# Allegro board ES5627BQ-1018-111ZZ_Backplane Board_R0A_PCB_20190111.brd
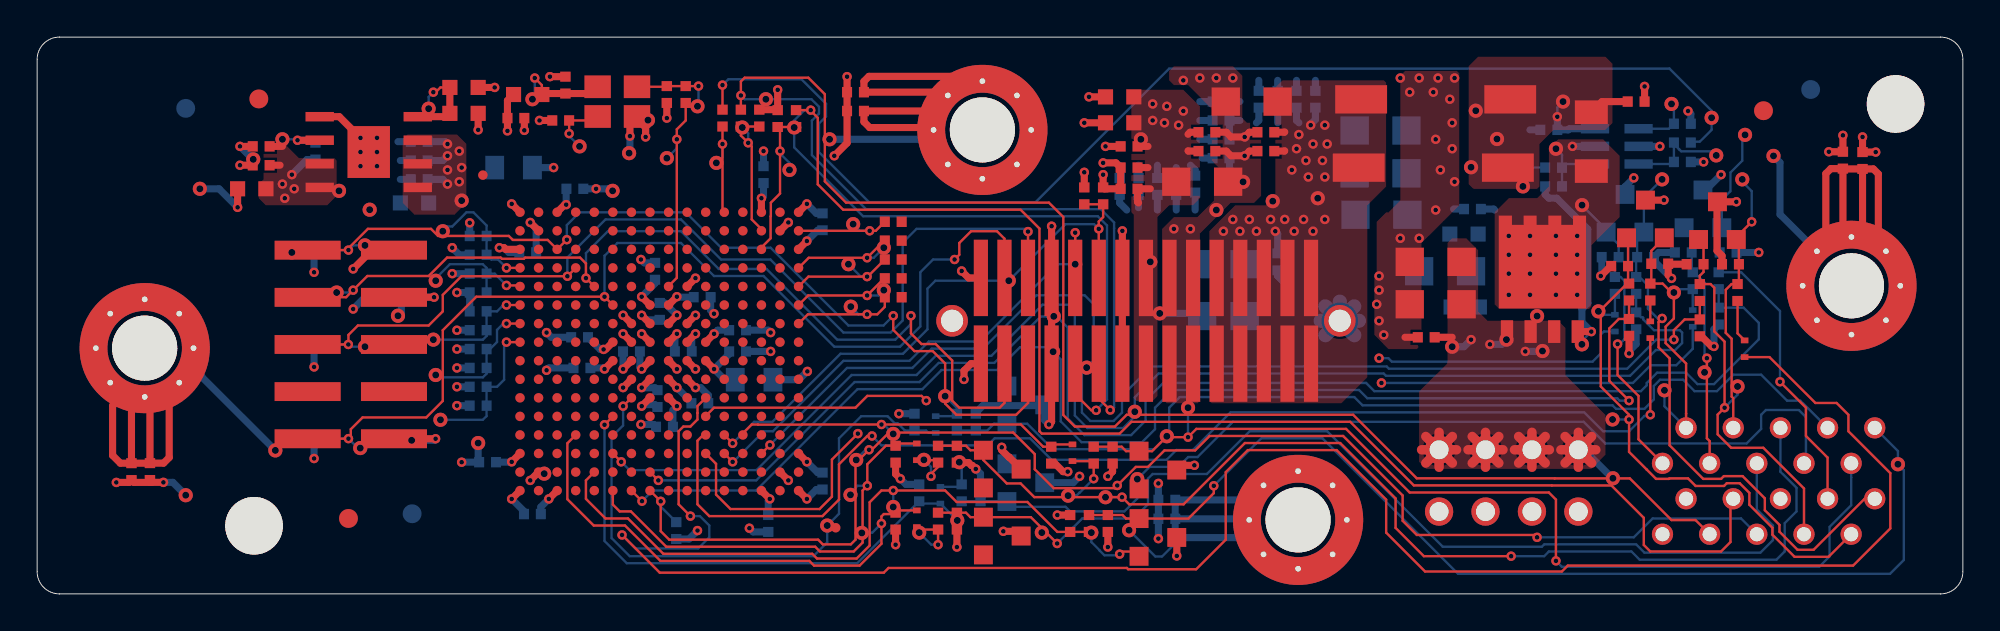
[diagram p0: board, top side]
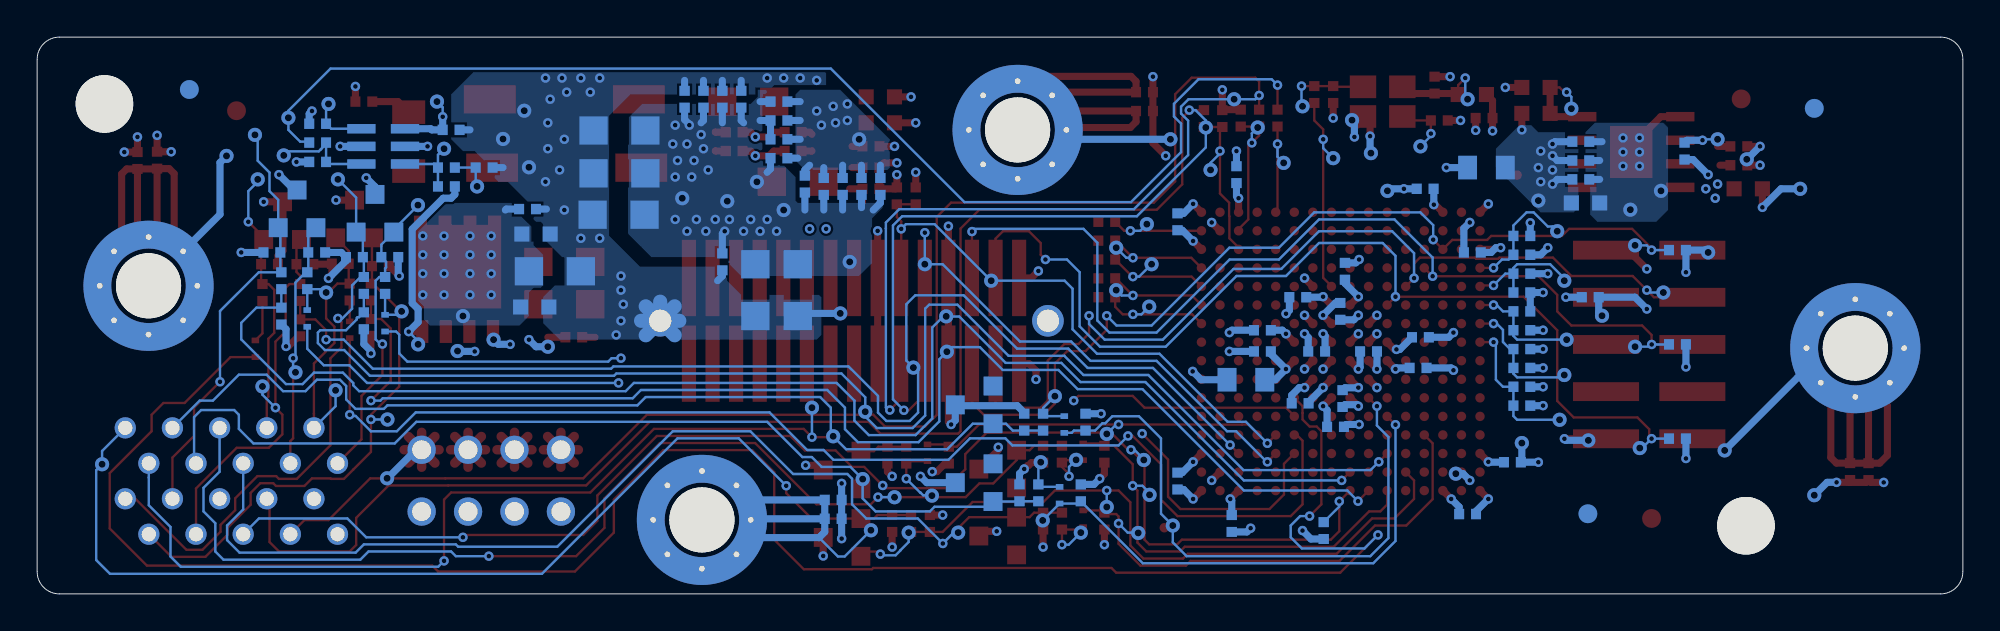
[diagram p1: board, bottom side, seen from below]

Outline 103.7 x 30 mm; copper layers: TOP, G2, V3, BOTTOM. Coordinates in mm from the lower left corner of the outline.
Outline path: 0,28.8 0,1.2 arc(0.35,0.35) 1.2,0 102.5,0 arc(103.35,0.35) 103.7,1.2 103.7,28.8 arc(103.35,29.65) 102.5,30 1.2,30 arc(0.35,29.65) 0,28.8

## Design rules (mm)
nets with their own width: min track width 0.381; nets GND

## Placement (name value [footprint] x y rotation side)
C2  100pF  [CC0402]  88.65 18.4 90 bottom
C3  100pF  [CC0402]  91.06 18.4 270 bottom
C7  100pF  [CC0402]  91.19 17.76 270 top
C8  100pF  [CC0402]  89.28 17.76 270 top
C9  100pF  [CC0402]  57.91 7.48 0 top
C10  100pF  [CC0402]  87.38 17.79 90 top
C11  100pF  [CC0402]  85.22 17.66 270 top
C12  100pF  [CC0402]  50.8 5.44 0 bottom
C13  100pF  [CC0402]  84.71 18.14 90 bottom
C14  100pF  [CC0402]  86.61 18.14 270 bottom
C16  100pF  [CC0402]  57.66 3.79 0 top
C17  100pF  [CC0402]  49.53 3.92 0 top
C22  100pF  [CC0402]  50.55 9.25 0 bottom
C23  100pF  [CC0402]  49.53 7.53 0 top
C31  0.1uF  [CC0402]  98.3 23.35 180 top
C32  0.1uF/16V  [CC0402]  20.07 15.99 270 bottom
C33  0.1uF  [CC0402]  44.07 26.02 270 top
C35  0.1uF  [CC0402]  44.07 27.03 270 top
C36  0.1uF  [CC0402]  97.24 23.37 180 top
C37  0.1uF/16V  [CC0402]  65.79 26.65 180 bottom
C38  0.1uF/16V  [CC0402]  63.75 24.49 270 bottom
C39  0.1uF/16V  [CC0402]  63.75 25.51 270 bottom
C40  0.1uF/16V  [CC0402]  63.75 26.53 270 bottom
C41  0.1uF/16V  [CC0402]  58.29 21.95 180 bottom
C42  22uF/16V  [CC1206]  75.82 17.38 270 bottom
C44  0.1uF/16V  [CC0402]  77.29 20.74 90 bottom
C48  0.1uF  [CC0402]  60.83 4.05 90 bottom
C49  0.1uF/16V  [CC0402]  86.11 26.53 270 top
C51  0.1uF/16V  [CC0402]  28.45 27.42 180 top
C52  0.1uF  [CC0402]  62.99 24.88 270 top
C53  0.01uF  [CC0402]  58.8 21.83 90 top
C54  0.1uF  [CC0402]  58.8 22.97 90 top
C55  @10pF  [CC0402]  33.91 26.91 180 top
C56  0.1uF/16V  [CC0402]  25.78 25.64 90 top
C57  22uF  [CC1206]  62.74 22.21 90 top
C58  0.1uF  [CC0402]  6.08 6.59 0 top
C59  0.1uF/16V  [CC0402]  20.57 22.34 90 bottom
C60  0.1uF/16V  [CC0402]  20.57 24.37 90 bottom
C61  0.1uF/16V  [CC0402]  20.57 23.35 90 bottom
C63  22uF/6.3V  [CC0603]  20.32 21.07 90 bottom
C65  0.1uF/16V  [CC0402]  74.8 13.83 270 top
C66  22uF/16V  [CC1206]  75.31 15.6 90 top
C67  22uF/16V  [CC1206]  75.31 17.89 90 top
C68  0.1uF  [CC0402]  60.83 5.06 90 bottom
C69  0.1uF  [CC0402]  5.08 6.59 0 top
C71  22uF/6.3V  [CC0603]  11.56 21.83 270 top
C74  0.1uF/16V  [CC0402]  12.06 24.11 270 top
C75  0.1uF/16V  [CC0402]  12.06 23.1 270 top
C76  0.1uF/16V  [CC0402]  81.41 25 90 bottom
C77  0.22uF  [CC0402]  88.6 25.33 270 bottom
C78  0.01uF/25V  [CC0402]  79.63 22.97 270 bottom
C79  1uF  [CC0603]  76.9 15.46 90 bottom
C80  10uF  [CC0603]  76.83 19.39 90 bottom
CB1  22uF/16V  [CC1206]  65.02 16.37 0 bottom
CB2  22uF/16V  [CC1206]  72.39 20.43 90 bottom
CB3  22uF/16V  [CC1206]  65.41 26.53 90 top
CB4  22uF/16V  [CC1206]  62.74 16.37 0 bottom
CB5  22uF/16V  [CC1206]  72.34 22.66 90 bottom
CB6  22uF/16V  [CC1206]  72.34 24.97 90 bottom
CB7  0.1uF/16V  [CC0402]  66.17 24.88 270 top
CB8  0.1uF/16V  [CC0402]  61.34 21.95 180 bottom
CB9  0.1uF/16V  [CC0402]  59.31 21.95 180 bottom
CB10  0.1uF/16V  [CC0402]  63.75 23.48 270 bottom
CB11  0.1uF/16V  [CC0402]  60.33 21.95 180 bottom
CB12  0.1uF/16V  [CC0402]  62.36 22.08 180 bottom
CB13  0.1uF/16V  [CC0402]  68.83 26.65 0 bottom
CB14  0.1uF/16V  [CC0402]  66.17 23.86 270 top
CB15  0.1uF/16V  [CC0402]  66.8 17.89 180 bottom
CB16  0.1uF/16V  [CC0402]  67.82 26.65 0 bottom
CB17  0.1uF/16V  [CC0402]  66.8 26.65 0 bottom
CB18  0.1uF/16V  [CC0402]  26.67 4.3 90 bottom
CB19  0.1uF/16V  [CC0402]  29.21 13.83 90 bottom
CB20  0.1uF/16V  [CC0402]  29.34 12.18 90 bottom
CB21  0.1uF/16V  [CC0402]  33.27 17.38 0 bottom
CB22  0.1uF/16V  [CC0402]  42.29 20.05 0 bottom
CB23  0.1uF/16V  [CC0402]  42.29 6.08 180 bottom
CB24  0.1uF/16V  [CC0402]  39.37 3.79 180 bottom
CB25  22uF/6.3V  [CC0805]  38.61 11.54 270 bottom
CB26  0.1uF/16V  [CC0402]  35.69 10.27 270 bottom
CB27  0.1uF/16V  [CC0402]  33.78 9 90 bottom
CB28  0.1uF/16V  [CC0402]  33.53 15.22 0 bottom
CB29  0.1uF/16V  [CC0402]  24.26 7.1 90 bottom
CB30  0.1uF/16V  [CC0402]  32 13.06 90 bottom
CB31  0.1uF/16V  [CC0402]  28.96 21.83 270 bottom
CB32  0.1uF/16V  [CC0402]  34.8 13.06 270 bottom
CB33  22uF/6.3V  [CC0805]  25.65 22.97 270 bottom
CB34  0.1uF/16V  [CC0402]  37.72 14.21 270 bottom
CB35  0.1uF/16V  [CC0402]  35.81 15.99 270 bottom
CB36  0.1uF/16V  [CC0402]  33.4 10.52 0 bottom
CB37  0.1uF/16V  [CC0402]  39.12 22.59 0 bottom
CB38  0.1uF/16V  [CC0402]  26.42 18.4 270 bottom
CB39  0.1uF/16V  [CC0402]  37.72 13.06 270 bottom
CB54  1000pF  [CC0402]  58.8 24.11 270 top
CB55  0.1uF/16V  [CC0402]  62.99 23.86 90 top
CB56  1uF  [CC0603]  58.29 26.78 270 top
CB57  10uF  [CC0603]  58.29 25.38 270 top
CONN6  PHED-SS010G1ABONE-B140  [CONNM_2D54X4D65_2X5SP_12D7W5L]  16.89 13.44 90 top
CONN56  5-104655-4  [CONN_1D27X4D62_2X15SP_22D14W]  59.71 14.72 180 top
D1  RB720M-30  [SOD923_D9_2SP_D8WD6L]  89.15 14.84 90 bottom
D2  RB720M-30  [SOD923_D9_2SP_D8WD6L]  55.75 7.6 270 top
D3  RB720M-30  [SOD923_D9_2SP_D8WD6L]  91.95 13.21 90 top
D4  RB720M-30  [SOD923_D9_2SP_D8WD6L]  48.64 5.32 90 bottom
D5  RB720M-30  [SOD923_D9_2SP_D8WD6L]  84.96 14.59 90 bottom
D6  RB720M-30  [SOD923_D9_2SP_D8WD6L]  47.37 4.05 270 top
D7  RB720M-30  [SOD923_D9_2SP_D8WD6L]  48.39 9.13 90 bottom
D8  RB720M-30  [SOD923_D9_2SP_D8WD6L]  47.37 7.65 270 top
D9  RB720M-30  [SOD923_D9_2SP_D8WD6L]  86.87 14.23 90 top
H1  SCREW3  [MTH_276C138D_8DP_OSP]  97.7 16.6 0 top
H2  SCREW5  [MTH_276C138D_8DP_OSP]  50.9 25 0 top
H3  SCREW2  [MTH_276C138D_8DP_OSP]  67.9 3.99 0 top
H4  SCREW6  [MTH_276C138D_8DP_OSP]  5.79 13.24 0 top
J8  C214B5-100A  [CONN_1D27X1D91_20DP_28D81W_PIP]  87.22 6.08 0 top
L1  100MHz  10A  [LC3312_1]  75.18 22.97 90 top
L2  100MHz  10A  [LC3312_1]  75.31 26.65 90 top
L3  100MHz/3A/30ohm  [LC0603]  26.42 26.91 270 top
NOREF  -  []  5.79 13.24 0 top
NOREF#2  -  []  0 0 0 top
NOREF#3  -  []  11.68 3.67 0 top
NOREF#4  -  []  67.9 3.99 0 top
NOREF#5  -  []  0.08 17.99 0 top
NOREF#6  -  [unnamed#2]  11.94 26.67 0 top
NOREF#7  -  []  97.7 16.6 0 top
NOREF#8  -  []  75.49 4.44 0 top
NOREF#9  -  []  100.08 26.4 0 top
NOREF#10  -  []  5.79 13.24 0 top
NOREF#11  -  []  103.7 1.2 0 top
NOREF#12  -  [unnamed#2]  92.96 26.04 0 top
NOREF#13  -  []  67.9 3.99 0 top
NOREF#14  -  []  1.2 30 0 top
NOREF#15  -  []  100.08 26.4 0 top
NOREF#16  -  []  97.7 16.6 0 top
NOREF#17  -  []  50.9 25 0 top
NOREF#18  -  []  75.49 4.44 0 top
NOREF#19  -  [unnamed#2]  11.68 3.67 0 top
NOREF#20  -  []  249.81 -104.66 0 top
NOREF#21  -  []  0 0 0 top
NOREF#22  -  []  70.15 14.72 0 top
NOREF#23  -  [unnamed#2]  16.76 4.06 0 top
NOREF#24  -  []  11.68 3.67 0 top
NOREF#25  -  []  70.15 14.72 0 top
NOREF#26  -  []  50.9 25 0 top
NOREF#27  -  []  16.89 13.44 0 top
NOREF#28  -  [unnamed#2]  100.08 26.4 0 top
NOREF#29  -  []  16.89 13.44 0 top
NOREF#30  -  [unnamed#2]  8 26.16 180 bottom
NOREF#31  -  [unnamed#2]  20.19 4.32 180 bottom
NOREF#32  -  [unnamed#2]  95.5 27.18 180 bottom
OSC1  25MHz  [OSC_1D6X2D12_4SP_2D5W3D2L1DH]  31.24 26.52 0 top
Q1  PJMBZ6V2  [SOT23_3SP_C1_C2_A]  89.7 20.75 180 bottom
Q2  PJMBZ6V2  [SOT23_3SP_C1_C2_A]  90.48 20.11 0 top
Q3  PJMBZ6V2  [SOT23_3SP_C1_C2_A]  86.61 20.2 0 top
Q4  PJMBZ6V2  [SOT23_3SP_C1_C2_A]  85.51 20.51 180 bottom
Q5  PJMBZ6V2  [SOT23_3SP_C1_C2_A]  60.35 6.67 270 top
Q6  PJMBZ6V2  [SOT23_3SP_C1_C2_A]  53.24 5.99 90 bottom
Q7  PJMBZ6V2  [SOT23_3SP_C1_C2_A]  60.35 3.04 270 top
Q8  PJMBZ6V2  [SOT23_3SP_C1_C2_A]  51.97 3.12 270 top
Q9  PJMBZ6V2  [SOT23_3SP_C1_C2_A]  53.24 10.18 90 bottom
Q10  PJMBZ6V2  [SOT23_3SP_C1_C2_A]  51.97 6.72 270 top
Q11  N-CH  [SO8_3D75X1D27_5SP]  81.06 16.96 270 top
R1  100  [RC0402]  89.15 16.87 180 bottom
R2  100  [RC0402]  90.55 16.87 0 bottom
R3  100  [RC0402]  91.57 16.24 0 top
R4  100  [RC0402]  89.53 16.24 180 top
R5  100  [RC0402]  56.9 7.48 0 top
R6  100  [RC0402]  49.78 5.44 0 bottom
R7  100  [RC0402]  84.96 16.62 180 bottom
R8  100  [RC0402]  86.11 16.62 0 bottom
R9  100  [RC0402]  48.51 3.92 0 top
R10  100  [RC0402]  49.53 9.25 0 bottom
R11  100  [RC0402]  48.51 7.53 0 top
R12  1K  [RC0402]  90.55 14.97 0 bottom
R13  1K  [RC0402]  89.53 14.33 180 top
R14  1K  [RC0402]  86.11 14.72 0 bottom
R15  100  [RC0402]  85.72 16.26 180 top
R16  100  [RC0402]  86.87 16.26 0 top
R18  100  [RC0402]  56.64 3.79 180 top
R20  4.7K  [RC0402]  54.61 7.48 0 top
R21  1K  [RC0402]  85.72 14.36 180 top
R22  4.7K  [RC0402]  47.5 5.44 0 bottom
R23  4.7K  [RC0402]  34.42 3.41 180 bottom
R24  4.7K  [RC0402]  46.23 3.92 0 top
R25  1K  [RC0402]  55.63 3.79 0 top
R26  4.7K  [RC0402]  47.24 9.25 0 bottom
R28  @0  [RC0402]  46.1 20.05 90 top
R29  @0  [RC0402]  46.1 19.03 90 top
R30  @0  [RC0402]  46.1 18.02 90 top
R31  @0  [RC0402]  46.1 17 90 top
R32  @0  [RC0402]  46.1 15.99 90 top
R33  0  [RC0402]  40.87 25.61 180 top
R34  @4.7K  [RC0402]  39.88 25.61 0 top
R35  0  [RC0402]  37.9 25.64 180 top
R36  @4.7K  [RC0402]  38.89 25.64 0 top
R37  0  [RC0402]  36.91 25.64 180 top
R38  10K  [RC0402]  57.4 21.45 180 top
R39  @10K  [RC0402]  56.39 21.45 0 top
R40  33  [RC0402]  34.92 26.91 180 top
R41  4.7K  [RC0402]  28.19 25.51 90 top
R43  10Kohm  [RC0603]  22.99 27.29 270 top
R44  4.7K  [RC0402]  46.23 7.53 0 top
R45  20Kohm  [RC0603]  22.99 25.89 270 top
R48  10K  [RC0402]  23.75 11.16 90 bottom
R49  @4.7K  [RC0402]  23.75 10.14 270 bottom
R50  4.7K  [RC0402]  23.75 12.18 270 bottom
R51  @10K  [RC0402]  23.75 13.19 90 bottom
R52  10K  [RC0402]  23.75 15.22 90 bottom
R53  @4.7K  [RC0402]  23.75 14.21 270 bottom
R54  4.7K  [RC0402]  23.75 17.26 270 bottom
R55  @10K  [RC0402]  23.75 16.24 90 bottom
R56  @10K  [RC0402]  23.75 18.27 90 bottom
R57  4.7K  [RC0402]  23.75 19.29 270 bottom
R58  10K  [RC0402]  15.37 13.45 90 bottom
R59  1K  [RC0402]  15.37 18.53 270 bottom
R61  4.7K  [RC0402]  14.99 23.86 180 bottom
R62  10K  [RC0402]  15.37 8.37 90 bottom
R63  0.005ohm/1206  [RC1206]  83.69 24.37 0 top
R65  10K  [RC0402]  88.6 24.32 270 bottom
R67  100  [RC0402]  81.66 22.97 90 bottom
R68  100  [RC0402]  81.66 21.95 90 bottom
R69  10K  [RC0402]  88.6 23.28 270 bottom
U1  5M1270ZF256I5N  [FBGA_1D_20C_256SP_17WL]  33.5 13.06 270 top
U2  AP7362-SP-13  [SOP_1D27X5D28_8SP_3D9W4D9L_G1]  17.86 23.81 0 top
U3  ADM4210-1AUJ-RL7  [SOT23_D95X2D35_6SP_1D6W2D9L]  85.06 24.11 270 bottom

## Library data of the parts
C2 C3 C7-C14 C16 C17 C22 C23 = C_NP: room: 31
C31-C33 C35 C36 C42 C44 C48 C51 C52 C54 C56 C58-C61 C63 C65-C69 C71 C74 C75 C77 C79 C80 CB1-CB7 CB13-CB39 CB54-CB57 = C_NP
C37-C41 C49 CB8-CB12 = CAP NP_4
C53 C57 C78 = C_NP: room: VCC10
C55 = C_NP: room: 159
C76 = CAP NP
CONN6 = PINSTICK_MALE_5PX2R
CONN56 = PINHEADER_MALE_15PX2R_G2
D1-D9 = SCHOTTKY1_1
H1-H4 = SKREW
J8 = C214B5-100A_0
L1 L2 = BEAD: room: 50
L3 = BEAD: room: 8
OSC1 = OSC_10
Q1-Q10 = DIODE2_3
Q11 = NMOS1_6
R1 R3 R5-R7 R9-R14 R16 R21 R25 R34 R36 R40 R58 R61-R63 R67 R68 = R: tolerance: 1%
R2 R4 R8 R15 R18 = R: room: 1
R20 R22-R24 R26 R44 = R: room: 26
R28-R33 R35 R37 = R: tolerance: 1%; room: U120
R38 R39 R41 R49 R50 R53 R54 R57 = R: tolerance: 1%; room: U83
R43 R45 R48 R51 R52 R55 R56 R65 R69 = R
R59 = R: tolerance: 1%; room: 41
U1 = CPLD_ALTERA_5M1270_FBGA256
U2 = LDO_DIODES_AP7362
U3 = HOT SWAP_ADI_ADM4210-1AUJ

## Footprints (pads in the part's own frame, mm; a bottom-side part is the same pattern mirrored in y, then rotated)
CC0402
  rect 0.559x0.539 smd: 1(0,0.454) 2(0,-0.454)
CC0603
  rect 0.813x0.813 smd: 1(0,0.762) 2(0,-0.762)
CC0805
  rect 1.27x1.016 smd: 1(0,1.016) 2(0,-1.016)
CC1206
  rect 1.524x1.524 smd: 1(0,1.397) 2(0,-1.397)
CONN_1D27X1D91_20DP_28D81W_PIP
  round 1.143 hole 0.762: 1(0.3,-2.865) 2(1.57,-0.955) 3(2.84,-2.865) 4(4.11,-0.955) 5(5.38,-2.865) 6(6.65,-0.955) 7(7.92,-2.865) 8(9.19,-0.955) 9(10.46,-2.865) 10(11.73,-0.955) 11(11.73,2.865) 12(10.46,0.955) 13(9.19,2.865) 14(7.92,0.955) 15(6.65,2.865) 16(5.38,0.955) 17(4.11,2.865) 18(2.84,0.955) 19(1.57,2.865) 20(0.3,0.955)
  round 1.524 hole 1.016: P1A1(-11.73,1.685) P1A2(-9.23,1.685) P1A3(-6.73,1.685) P1A4(-4.23,1.685) P1B1(-11.73,-1.645) P1B2(-9.23,-1.645) P1B3(-6.73,-1.645) P1B4(-4.23,-1.645)
CONN_1D27X4D62_2X15SP_22D14W
  rect 0.762x4.115 smd: 1(-8.89,-2.31) 2(-8.89,2.31) 3(-7.62,-2.31) 4(-7.62,2.31) 5(-6.35,-2.31) 6(-6.35,2.31) 7(-5.08,-2.31) 8(-5.08,2.31) 9(-3.81,-2.31) 10(-3.81,2.31) 11(-2.54,-2.31) 12(-2.54,2.31) 13(-1.27,-2.31) 14(-1.27,2.31) 15(0,-2.31) 16(0,2.31) 17(1.27,-2.31) 18(1.27,2.31) 19(2.54,-2.31) 20(2.54,2.31) 21(3.81,-2.31) 22(3.81,2.31) 23(5.08,-2.31) 24(5.08,2.31) 25(6.35,-2.31) 26(6.35,2.31) 27(7.62,-2.31) 28(7.62,2.31) 29(8.89,-2.31) 30(8.89,2.31)
  round 1.702 hole 1.194: G1(-10.44,0) G2(10.44,0)
CONNM_2D54X4D65_2X5SP_12D7W5L
  rect 1.016x3.556 smd: 1(5.08,2.325) 2(5.08,-2.325) 3(2.54,2.325) 4(2.54,-2.325) 5(0,2.325) 6(0,-2.325) 7(-2.54,2.325) 8(-2.54,-2.325) 9(-5.08,2.325) 10(-5.08,-2.325)
FBGA_1D_20C_256SP_17WL
  round 0.508 smd: (-9.5,-9.5) (9.5,9.5) A1(-7.5,7.5) A2(-6.5,7.5) A3(-5.5,7.5) A4(-4.5,7.5) A5(-3.5,7.5) A6(-2.5,7.5) A7(-1.5,7.5) A8(-0.5,7.5) A9(0.5,7.5) A10(1.5,7.5) A11(2.5,7.5) A12(3.5,7.5) A13(4.5,7.5) A14(5.5,7.5) A15(6.5,7.5) A16(7.5,7.5) B1(-7.5,6.5) B2(-6.5,6.5) B3(-5.5,6.5) B4(-4.5,6.5) B5(-3.5,6.5) B6(-2.5,6.5) B7(-1.5,6.5) B8(-0.5,6.5) B9(0.5,6.5) B10(1.5,6.5) B11(2.5,6.5) B12(3.5,6.5) B13(4.5,6.5) B14(5.5,6.5) B15(6.5,6.5) B16(7.5,6.5) C1(-7.5,5.5) C2(-6.5,5.5) C3(-5.5,5.5) C4(-4.5,5.5) C5(-3.5,5.5) C6(-2.5,5.5) C7(-1.5,5.5) C8(-0.5,5.5) C9(0.5,5.5) C10(1.5,5.5) C11(2.5,5.5) C12(3.5,5.5) C13(4.5,5.5) C14(5.5,5.5) C15(6.5,5.5) C16(7.5,5.5) D1(-7.5,4.5) D2(-6.5,4.5) D3(-5.5,4.5) D4(-4.5,4.5) D5(-3.5,4.5) D6(-2.5,4.5) D7(-1.5,4.5) D8(-0.5,4.5) D9(0.5,4.5) D10(1.5,4.5) D11(2.5,4.5) D12(3.5,4.5) D13(4.5,4.5) D14(5.5,4.5) D15(6.5,4.5) D16(7.5,4.5) E1(-7.5,3.5) E2(-6.5,3.5) E3(-5.5,3.5) E4(-4.5,3.5) E5(-3.5,3.5) E6(-2.5,3.5) E7(-1.5,3.5) E8(-0.5,3.5) E9(0.5,3.5) E10(1.5,3.5) E11(2.5,3.5) E12(3.5,3.5) E13(4.5,3.5) E14(5.5,3.5) E15(6.5,3.5) E16(7.5,3.5) F1(-7.5,2.5) F2(-6.5,2.5) F3(-5.5,2.5) F4(-4.5,2.5) F5(-3.5,2.5) F6(-2.5,2.5) F7(-1.5,2.5) F8(-0.5,2.5) F9(0.5,2.5) F10(1.5,2.5) F11(2.5,2.5) F12(3.5,2.5) F13(4.5,2.5) F14(5.5,2.5) F15(6.5,2.5) F16(7.5,2.5) G1(-7.5,1.5) G2(-6.5,1.5) G3(-5.5,1.5) G4(-4.5,1.5) G5(-3.5,1.5) G6(-2.5,1.5) G7(-1.5,1.5) G8(-0.5,1.5) G9(0.5,1.5) G10(1.5,1.5) G11(2.5,1.5) G12(3.5,1.5) G13(4.5,1.5) G14(5.5,1.5) G15(6.5,1.5) G16(7.5,1.5) H1(-7.5,0.5) H2(-6.5,0.5) H3(-5.5,0.5) H4(-4.5,0.5) H5(-3.5,0.5) H6(-2.5,0.5) H7(-1.5,0.5) H8(-0.5,0.5) H9(0.5,0.5) H10(1.5,0.5) H11(2.5,0.5) H12(3.5,0.5) H13(4.5,0.5) H14(5.5,0.5) H15(6.5,0.5) H16(7.5,0.5) J1(-7.5,-0.5) J2(-6.5,-0.5) J3(-5.5,-0.5) J4(-4.5,-0.5) J5(-3.5,-0.5) J6(-2.5,-0.5) J7(-1.5,-0.5) J8(-0.5,-0.5) J9(0.5,-0.5) J10(1.5,-0.5) J11(2.5,-0.5) J12(3.5,-0.5) J13(4.5,-0.5) J14(5.5,-0.5) J15(6.5,-0.5) J16(7.5,-0.5) K1(-7.5,-1.5) K2(-6.5,-1.5) K3(-5.5,-1.5) K4(-4.5,-1.5) K5(-3.5,-1.5) K6(-2.5,-1.5) K7(-1.5,-1.5) K8(-0.5,-1.5) K9(0.5,-1.5) K10(1.5,-1.5) K11(2.5,-1.5) K12(3.5,-1.5) K13(4.5,-1.5) K14(5.5,-1.5) K15(6.5,-1.5) K16(7.5,-1.5) L1(-7.5,-2.5) L2(-6.5,-2.5) L3(-5.5,-2.5) L4(-4.5,-2.5) L5(-3.5,-2.5) L6(-2.5,-2.5) L7(-1.5,-2.5) L8(-0.5,-2.5) L9(0.5,-2.5) L10(1.5,-2.5) L11(2.5,-2.5) L12(3.5,-2.5) L13(4.5,-2.5) L14(5.5,-2.5) L15(6.5,-2.5) L16(7.5,-2.5) M1(-7.5,-3.5) M2(-6.5,-3.5) M3(-5.5,-3.5) M4(-4.5,-3.5) M5(-3.5,-3.5) M6(-2.5,-3.5) M7(-1.5,-3.5) M8(-0.5,-3.5) M9(0.5,-3.5) M10(1.5,-3.5) M11(2.5,-3.5) M12(3.5,-3.5) M13(4.5,-3.5) M14(5.5,-3.5) M15(6.5,-3.5) M16(7.5,-3.5) N1(-7.5,-4.5) N2(-6.5,-4.5) N3(-5.5,-4.5) N4(-4.5,-4.5) N5(-3.5,-4.5) N6(-2.5,-4.5) N7(-1.5,-4.5) N8(-0.5,-4.5) N9(0.5,-4.5) N10(1.5,-4.5) N11(2.5,-4.5) N12(3.5,-4.5) N13(4.5,-4.5) N14(5.5,-4.5) N15(6.5,-4.5) N16(7.5,-4.5) P1(-7.5,-5.5) P2(-6.5,-5.5) P3(-5.5,-5.5) P4(-4.5,-5.5) P5(-3.5,-5.5) P6(-2.5,-5.5) P7(-1.5,-5.5) P8(-0.5,-5.5) P9(0.5,-5.5) P10(1.5,-5.5) P11(2.5,-5.5) P12(3.5,-5.5) P13(4.5,-5.5) P14(5.5,-5.5) P15(6.5,-5.5) P16(7.5,-5.5) R1(-7.5,-6.5) R2(-6.5,-6.5) R3(-5.5,-6.5) R4(-4.5,-6.5) R5(-3.5,-6.5) R6(-2.5,-6.5) R7(-1.5,-6.5) R8(-0.5,-6.5) R9(0.5,-6.5) R10(1.5,-6.5) R11(2.5,-6.5) R12(3.5,-6.5) R13(4.5,-6.5) R14(5.5,-6.5) R15(6.5,-6.5) R16(7.5,-6.5) T1(-7.5,-7.5) T2(-6.5,-7.5) T3(-5.5,-7.5) T4(-4.5,-7.5) T5(-3.5,-7.5) T6(-2.5,-7.5) T7(-1.5,-7.5) T8(-0.5,-7.5) T9(0.5,-7.5) T10(1.5,-7.5) T11(2.5,-7.5) T12(3.5,-7.5) T13(4.5,-7.5) T14(5.5,-7.5) T15(6.5,-7.5) T16(7.5,-7.5)
LC0603
  rect 0.813x0.813 smd: 1(0,0.762) 2(0,-0.762)
LC3312_1
  rect 1.524x2.794 smd: 1(0,4.015) 2(0,-4.015)
MTH_276C138D_8DP_OSP
  round 3.505 hole 3.505 unplated: (0,0)
  round 0.889 hole 0.305: 1(0,2.629) 2(1.859,1.859) 3(2.629,0) 4(1.859,-1.859) 5(0,-2.629) 6(-1.859,-1.859) 7(-2.629,0) 8(-1.859,1.859)
OSC_1D6X2D12_4SP_2D5W3D2L1DH
  rect 1.422x1.219 smd: 1(-1.06,-0.8) 2(1.06,-0.8) 3(1.06,0.8) 4(-1.06,0.8)
RC0402
  rect 0.559x0.539 smd: 1(0,0.454) 2(0,-0.454)
RC0603
  rect 0.813x0.813 smd: 1(0,0.762) 2(0,-0.762)
RC1206
  rect 1.778x1.27 smd: 1(0,1.587) 2(0,-1.587)
SO8_3D75X1D27_5SP
  rect 1.219x0.66 smd: 1(2.825,-1.905) 2(2.825,-0.635) 3(2.825,0.635) 4(2.825,1.905)
  custom 1.175x1.175 smd: 5(-0.925,0)
SOD923_D9_2SP_D8WD6L
  rect 0.305x0.406 smd: A(-0.45,0) C(0.45,0)
SOP_1D27X5D28_8SP_3D9W4D9L_G1
  rect 1.524x0.508 smd: 1(-2.64,1.905) 2(-2.64,0.635) 3(-2.64,-0.635) 4(-2.64,-1.905) 5(2.64,-1.905) 6(2.64,-0.635) 7(2.64,0.635) 8(2.64,1.905)
  rect 2.286x2.794 smd: G1(0,0)
SOT23_3SP_C1_C2_A
  rect 1.016x1.016 smd: A(0,1.016) C1(-1.016,-1.016) C2(1.016,-1.016)
SOT23_D95X2D35_6SP_1D6W2D9L
  rect 0.508x1.524 smd: 1(-0.95,-1.175) 2(0,-1.175) 3(0.95,-1.175) 4(0.95,1.175) 5(0,1.175) 6(-0.95,1.175)
unnamed#2
  round 1.016 smd: (0,0)

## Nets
12V_FAN: C65.1 C66.2 C67.2 J8.P1A1 J8.P1A2 J8.P1A3 J8.P1A4 Q11.1(S1) Q11.2(S2) Q11.3(S3)
GND: C2.2 C3.2 C7.2 C8.2 C9.2 C10.2 C11.2 C12.2 C13.2 C14.2 C16.2 C17.2 C22.2 C23.2 C31.2 C32.1 C33.2 C35.2 C36.2 C37.1 C42.1 C44.2 C48.2 C49.1 C51.2 C52.1 C53.1 C54.1 C55.1 C56.2 C57.2 C58.2 C59.2 C60.2 C61.2 C63.2 C65.2 C66.1 C67.1 C68.2 C69.2 C71.2 C74.2 C75.2 C76.2 C77.2 C78.1 C79.2 C80.2 CB1.1 CB2.1 CB3.1 CB4.1 CB5.1 CB6.1 CB7.2 CB13.2 CB14.2 CB15.2 CB16.2 CB17.2 CB18.2 CB19.2 CB20.2 CB21.2 CB22.2 CB23.2 CB24.2 CB25.2 CB26.2 CB27.2 CB28.2 CB29.2 CB30.2 CB31.2 CB32.2 CB33.2 CB34.2 CB35.2 CB36.2 CB37.2 CB38.2 CB39.2 CB54.2 CB55.2 CB56.2 CB57.2 CONN6.2 CONN6.10 CONN56.11 CONN56.12 CONN56.13 CONN56.14 CONN56.17 CONN56.18 CONN56.23 CONN56.24 CONN56.29 CONN56.30 CONN56.G1 CONN56.G2 J8.2 J8.6 J8.P1B1 J8.P1B2 J8.P1B3 J8.P1B4 OSC1.2(GND) Q1.A Q2.A Q3.A Q4.A Q5.A Q6.A Q7.A Q8.A Q9.A Q10.A R38.2 R43.1 R48.2 R51.2 R52.2 R55.2 R56.2 R59.1 R69.2 U1.A1(GNDIO_1) U1.A16(GNDIO_2) U1.B2(GNDIO_4) U1.B15(GNDIO_3) U1.G5(GNDIO_6) U1.G7(GNDIO_7) U1.G8(GNDIO_8) U1.G9(GNDIO_9) U1.G10(GNDIO_5) U1.H7(GNDINT_1) U1.H9(GNDINT_2) U1.J8(GNDINT_4) U1.J10(GNDINT_3) U1.K7(GNDIO_11) U1.K8(GNDIO_12) U1.K9(GNDIO_13) U1.K10(GNDIO_10) U1.R2(GNDIO_15) U1.R15(GNDIO_14) U1.T1(GNDIO_16) U1.T16(GNDIO_17) U2.1(GND) U2.G1 U3.2(GND)
25MHZ_OUT: C55.2 OSC1.3(OUT) R40.2
25MHZ_OUT_R: R40.1 U1.H5(IO_1_H5/CLK0)
ALARM1: D3.A U1.F11(IO_3_F11/DIFFIO_R6N)
ALARM1_D: D3.C R3.2
ALARM1_R: C7.1 J8.17 Q2.C2 R3.1
ALARM2: D1.A U1.F12(IO_3_F12/DIFFIO_R5N)
ALARM2_D: D1.C R1.2
ALARM2_R: C2.1 J8.18 Q1.C2 R1.1
ALARM3: D9.A U1.F13(IO_3_F13/DIFFIO_R4N)
ALARM3_D: D9.C R16.2
ALARM3_R: C10.1 J8.19 Q3.C2 R16.1
ALARM4: D5.A U1.F14(IO_3_F14/DIFFIO_R3N)
ALARM4_D: D5.C R7.2
ALARM4_R: C13.1 J8.20 Q4.C2 R7.1
BOARD_ID_1: R56.1 R57.2 U1.T4(IO_4_T4/DIFFIO_B5P)
BOARD_ID_2: R54.2 R55.1 U1.T5(IO_4_T5/DIFFIO_B7P)
CPLD_TCK: CONN6.1 CONN56.26 R59.2 U1.P3(TCK)
CPLD_TDI: CONN6.9 CONN56.27 R62.1 U1.L6(TDI)
CPLD_TDO: CONN6.3 CONN56.28 U1.M5(TDO)
CPLD_TMS: CONN6.5 CONN56.25 R58.1 U1.N4(TMS)
CPU_I2C_R_SCL: R33.1 R34.2 U1.C3(IO_1_C3/DIFFIO_L2P)
CPU_I2C_R_SDA: R35.1 R36.2 U1.C2(IO_1_C2/DIFFIO_L1N)
CPU_I2C_SCL: CONN56.22 J8.4 R33.2
CPU_I2C_SDA: CONN56.20 J8.3 R35.2
FAN1_CTL_R: C8.1 J8.7 Q2.C1 R4.2
FAN1_SENSOR: D2.A R20.1 U1.D13(IO_3_D13)
FAN1_SENSOR_D: D2.C R5.2
FAN1_SENSOR_R: C9.1 J8.12 Q5.C1 R5.1
FAN2_CTL_R: C3.1 J8.8 Q1.C1 R2.2
FAN2_SENSOR: D7.A R26.1 U1.K11(IO_3_K11)
FAN2_SENSOR_D: D7.C R10.2
FAN2_SENSOR_R: C22.1 J8.13 Q9.C1 R10.1
FAN3_CTL_R: C11.1 J8.9 Q3.C1 R15.2
FAN3_SENSOR: D4.A R22.1 U1.L12(IO_3_L12/DIFFIO_R19N)
FAN3_SENSOR_D: D4.C R6.2
FAN3_SENSOR_R: C12.1 J8.14 Q6.C1 R6.1
FAN4_CTL_R: C14.1 J8.10 Q4.C1 R8.2
FAN4_SENSOR: D8.A R44.1 U1.L16(IO_3_L16/DIFFIO_R17P)
FAN4_SENSOR_D: D8.C R11.2
FAN4_SENSOR_R: C23.1 J8.15 Q10.C1 R11.1
FAN5_CTL_R: C16.1 J8.11 Q7.C1 R18.2
FAN5_SENSOR: D6.A R24.1 U1.N13(IO_3_N13/DIFFIO_R24P)
FAN5_SENSOR_D: D6.C R9.2
FAN5_SENSOR_R: C17.1 J8.16 Q8.C1 R9.1
FAN_1V8: C59.1 C60.1 C61.1 C63.1 CB26.1 CB28.1 CB30.1 CB32.1 CB33.1 R45.1 U1.H8(VCCINT_1) U1.H10(VCCINT_2) U1.J7(VCCINT_3) U1.J9(VCCINT_4) U2.5(OUT_1) U2.6(OUT_2) U2.7(OUT_3)
FAN_IDLE: CONN56.19 R38.1 R39.2 U1.E13(IO_3_E13/DIFFIO_R2N)
FAN_IN_3V3_25M_EN: OSC1.1(\\S\T/OE) R41.2
FAN_IN_3V3_25M_VCC: C51.1 L3.1 OSC1.4(VDD)
FAN_IN_3V3_EN: R61.1 U2.2(EN)
FAN_INT: CONN56.21 U1.E14(IO_3_E14/DIFFIO_R1P)
FAN_PRESENT: J8.5 Q7.C2 R23.1 U1.J16(IO_3_J16/DIFFIO_R13N)
FAN_PW_EN: R37.1 U1.E1(IO_1_E1/DIFFIO_L6P)
FAN_PW_EN_R: R37.2 R65.2
FAN_PWM_1: R4.1 R13.2 U1.C14(IO_3_C14/DIFFIO_R1N)
FAN_PWM_2: R2.1 R12.2 U1.J15(IO_3_J15/DIFFIO_R14N)
FAN_PWM_3: R15.1 R21.2 U1.K16(IO_3_K16/DIFFIO_R15P)
FAN_PWM_4: R8.1 R14.2 U1.L14(IO_3_L14/DIFFIO_R21P)
FAN_PWM_5: R18.1 R25.2 U1.M15(IO_3_M15)
FAN_VP3P3: C32.2 C38.1 C39.1 C40.1 C41.1 C52.2 C53.2 C54.2 C56.1 C57.1 C71.1 C74.1 C75.1 CB8.1 CB9.1 CB10.1 CB11.1 CB12.1 CB18.1 CB19.1 CB20.1 CB21.1 CB22.1 CB23.1 CB24.1 CB25.1 CB27.1 CB29.1 CB31.1 CB34.1 CB35.1 CB36.1 CB37.1 CB38.1 CB39.1 CB54.1 CB55.1 CB56.1 CB57.1 CONN6.4 CONN56.15 CONN56.16 J8.1 L3.2 R12.1 R13.1 R14.1 R20.2 R21.1 R22.2 R23.2 R24.2 R25.1 R26.2 R34.1 R36.1 R39.1 R41.1 R44.2 R49.1 R50.1 R53.1 R54.1 R57.1 R58.2 R61.2 R62.2 U1.A3(VCCIO2_4) U1.A14(VCCIO2_1) U1.C1(VCCIO1_1) U1.C16(VCCIO3_4) U1.F8(VCCIO2_3) U1.F9(VCCIO2_2) U1.H6(VCCIO1_2) U1.H11(VCCIO3_3) U1.J6(VCCIO1_3) U1.J11(VCCIO3_2) U1.L8(VCCIO4_2) U1.L9(VCCIO4_3) U1.P1(VCCIO1_4) U1.P16(VCCIO3_1) U1.T3(VCCIO4_1) U1.T14(VCCIO4_4) U2.3(IN_1) U2.4(IN_2)
FAN_VP12: C37.2 C38.2 C39.2 C40.2 C41.2 CB1.2 CB2.2 CB3.2 CB4.2 CB5.2 CB6.2 CB7.1 CB8.2 CB9.2 CB10.2 CB11.2 CB12.2 CB13.1 CB14.1 CB15.1 CB16.1 CB17.1 CONN56.1 CONN56.2 CONN56.3 CONN56.4 CONN56.5 CONN56.6 CONN56.7 CONN56.8 CONN56.9 CONN56.10 L1.1 L2.1
FAN_VP12_R: C49.2 C76.1 L1.2 L2.2 R63.1 U3.6(VCC)
FB_3P3_1P8: R43.2 R45.2 U2.8(ADJ/NC)
HGATE_MB1: Q11.4(G) R68.2
HOLE_2: C48.1 C68.1 H3.1 H3.2 H3.3 H3.4 H3.5 H3.6 H3.7 H3.8
HOLE_3: C31.1 C36.1 H1.1 H1.2 H1.3 H1.4 H1.5 H1.6 H1.7 H1.8
HOLE_5: C33.1 C35.1 H2.1 H2.2 H2.3 H2.4 H2.5 H2.6 H2.7 H2.8
HOLE_6: C58.1 C69.1 H4.1 H4.2 H4.3 H4.4 H4.5 H4.6 H4.7 H4.8
RESERVED_1: R28.1 U1.A2(IO_2_A2/DIFFIO_T2P)
RESERVED_2: R29.1 U1.A4(IO_2_A4/DIFFIO_T5P)
RESERVED_3: R30.1 U1.A5(IO_2_A5/DIFFIO_T6P)
RESERVED_4: R31.1 U1.A6(IO_2_A6/DIFFIO_T8N)
RESERVED_5: R32.1 U1.A7(IO_2_A7/DIFFIO_T10P)
SENSE_12V: C42.2 C44.1 C79.1 C80.1 Q11.5(D) R63.2 U3.5(SENSE)
VERSION_ID_1: R52.1 R53.2 U1.T6(IO_4_T6/DIFFIO_B9P)
VERSION_ID_2: R50.2 R51.1 U1.T7(IO_4_T7/DIFFIO_B10N)
VERSION_ID_3: R48.1 R49.2 U1.T8(IO_4_T8/DIFFIO_B12N)
N65528284: C77.1 U3.1(TIMER)
N65531777: R65.1 R69.1 U3.3(ON)
N65532055: C78.2 R67.2
N65533374: R67.1 R68.1 U3.4(GATE)

Pads without a net: CONN6 6 7 8; Q5 C2; Q6 C2; Q8 C2; Q9 C2; Q10 C2; R28 2; R29 2; R30 2; R31 2; R32 2; U1 A8 A9 A10 A11 A12 A13 A15 B1 B3 B4 B5 B6 B7 B8 B9 B10 B11 B12 B13 B14 B16 C4 C5 C6 C7 C8 C9 C10 C11 C12 C13 C15 D1 D2 D3 D4 D5 D6 D7 D8 D9 D10 D11 D12 D14 D15 D16 E2 E3 E4 E5 E6 E7 E8 E9 E10 E11 E12 E15 E16 F1 F2 F3 F4 F5 F6 F7 F10 F15 F16 G1 G2 G3 G4 G6 G11 G12 G13 G14 G15 G16 H1 H2 H3 H4 H12 H13 H14 H15 H16 J1 J2 J3 J4 J5 J12 J13 J14 K1 K2 K3 K4 K5 K6 K12 K13 K14 K15 L1 L2 L3 L4 L5 L7 L10 L11 L13 L15 M1 M2 M3 M4 M6 M7 M8 M9 M10 M11 M12 M13 M14 M16 N1 N2 N3 N5 N6 N7 N8 N9 N10 N11 N12 N14 N15 N16 P2 P4 P5 P6 P7 P8 P9 P10 P11 P12 P13 P14 P15 R1 R3 R4 R5 R6 R7 R8 R9 R10 R11 R12 R13 R14 R16 T2 T9 T10 T11 T12 T13 T15

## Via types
v1: diameter 0.508, hole 0.254, TOP to BOTTOM, 309 vias
v2: diameter 0.762, hole 0.381, TOP to BOTTOM, 100 vias

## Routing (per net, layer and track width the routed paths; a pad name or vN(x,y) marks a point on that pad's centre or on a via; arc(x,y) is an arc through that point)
12V_FAN: length 37.8
  TOP w0.381: C65.1 76.2,13.83
  TOP w0.508: J8.P1A4 82.99,8.71 ; J8.P1A4 82.99,6.82 ; J8.P1A4 82.28,8.48 ; J8.P1A4 82.05,7.77 ; J8.P1A4 82.28,7.05 ; J8.P1A4 83.71,7.05 ; J8.P1A4 83.71,8.48 ; J8.P1A4 83.94,7.77 ; 77.99,6.82 J8.P1A2 ; J8.P1A2 77.05,7.77 ; J8.P1A2 78.94,7.77 ; J8.P1A2 77.99,8.71 ; J8.P1A2 78.71,8.48 ; J8.P1A2 77.28,7.05 ; J8.P1A2 77.28,8.48 ; J8.P1A2 78.71,7.05 ; 75.49,6.82 J8.P1A1 ; J8.P1A1 74.78,7.05 ; J8.P1A1 76.21,8.48 ; J8.P1A1 75.49,8.71 ; J8.P1A1 74.78,8.48 ; J8.P1A1 74.55,7.77 ; J8.P1A1 76.21,7.05 ; J8.P1A1 76.44,7.77 ; J8.P1A3 81.44,7.77 ; J8.P1A3 79.55,7.77 ; J8.P1A3 79.78,7.05 ; J8.P1A3 80.49,6.82 ; J8.P1A3 81.21,7.05 ; J8.P1A3 81.21,8.48 ; J8.P1A3 79.78,8.48 ; J8.P1A3 80.49,8.71
  BOTTOM w0.381: v2(81.06,13.09) 81.04,13.06 v1(80.14,13.06) ; v1(77.22,13.7) 76.83,13.32 v2(76.2,13.32) ; v2(79.12,13.7) 78.87,13.45 v1(78.23,13.45) ; v2(84.86,6.23) 84.83,6.23 83.29,7.77 J8.P1A4
GND: length 234
  TOP w0.381: v1(96.48,23.82) C36.2 v1(97.24,24.71) ; v1(88.01,17) 87.83,17.18 C10.2 87.86,17.76 C8.2 ; v1(51.94,7.9) 51.94,7.75 52.32,7.37 52.35,7.37 Q10.A ; U1.H9 v1(34.45,12.12) ; C55.1 v1(33.91,25.64) ; U1.J10 v1(32.55,11.12) ; C17.2 v1(49.53,2.52) ; C11.2 84.73,17.66 v1(84.2,17.13) ; R43.1 v1(24.64,27.29) ; CONN6.2 18.03,18.52 v1(17.02,17.51) ; C16.2 v1(57.66,2.52) ; C9.2 57.91,6.59 v1(57.66,6.33) ; C52.1 64.03,24.88 64.29,24.62 v1(65.02,24.62) 65.28,24.88 CB7.2 ; Q5.A 61.62,6.93 v1(62.32,6.93) ; v1(91.5,21.13) Q2.A 90.46,21.11 90.46,18.49 90.73,18.22 C7.2 ; v1(31.92,24.67) 31.92,25.34 OSC1.2 32.3,25.59 32.77,25.13 v1(32.77,24.62) ; U1.K7 v1(31.55,15.01) ; CONN56.18 CONN56.17 v1(58.44,19.56) ; v1(98.3,24.62) C31.2 v1(99.01,23.81) ; C23.2 50.16,7.07 50.32,6.91 50.36,6.91 v1(50.55,6.73) ; CB56.2 v1(56.64,26.78) ; CB55.2 64.03,23.86 64.29,23.61 v1(65.02,23.61) 65.28,23.86 CB14.2 ; CB57.2 v1(56.39,25.38) ; U1.T16 v1(25.55,5.12) ; U1.G9 v1(35.45,12.12) ; v1(54.63,19.81) CONN56.23 CONN56.24 54.63,9.27 v1(54.48,9.13) ; Q3.A v1(87.6,21.22) ; U1.A1 v1(41.45,21.01) ; Q7.A v1(61.37,2.04) ; v1(57.4,22.59) R38.2 57.48,21.83 C53.1 C54.1 58.09,23.22 v1(57.4,23.22) ; v1(49.91,11.56) 49.91,12.02 50.29,12.41 CONN56.30 ; v1(42.93,23.61) 43.61,24.29 C33.2 C35.2 v1(43.61,27.87) ; U1.K9 v1(31.55,12.12) ; CONN6.10 v1(21.46,8.36) ; v1(4.26,6.01) 4.95,6.01 C69.2 5.21,6.01 6.07,6.01 6.08,6.01 C58.2 6.2,6.01 v1(6.8,6.01) ; U2.1 16.27,25.71 v1(17.41,24.57) ; Q8.A 52.73,3.37 v1(52.03,3.37) ; U1.T1 v1(25.55,21.01) ; U1.G7 v1(35.45,15.01) ; U1.G10 v1(35.45,11.12) ; C75.2 v1(10.92,23.1) ; U1.K10 v1(31.55,11.12) ; v1(49.78,17.4) 50.16,17.03 CONN56.29 ; C71.2 v1(10.79,20.83) ; U1.B2 v1(40.45,20.01) ; U1.J8 v1(32.55,14.01) ; U1.G8 v1(35.45,14.01) ; U1.R15 v1(26.55,6.12) ; U1.K8 v1(31.55,14.01) ; U1.A16 v1(41.45,5.12) ; U1.R2 v1(26.55,20.01) ; C65.2 73.66,13.83 ; C49.1 v1(86.56,27.34) ; C51.2 v1(27.61,27.87) ; U1.H7 v1(34.45,15.01) ; U1.G5 v1(35.45,17.01) ; C74.2 v1(10.92,24.11) ; C56.2 v1(26.24,24.98) ; U1.B15 v1(40.45,6.12) ; CB54.2 v1(57.53,24.11)
  G2 w0.635: J8.P1B1 76.44,4.44 ; J8.P1B1 74.78,3.72 ; J8.P1B1 74.55,4.44 ; J8.P1B1 74.78,5.15 ; J8.P1B1 76.21,3.72 ; J8.P1B1 75.49,5.38 ; J8.P1B1 76.21,5.15 ; J8.P1B1 75.49,3.49 ; 69.37,13.94 CONN56.G1 ; CONN56.G1 70.15,15.74 ; CONN56.G1 70.93,15.49 ; CONN56.G1 70.93,13.94 ; CONN56.G1 71.18,14.72 ; CONN56.G1 69.12,14.72 ; CONN56.G1 69.37,15.49 ; CONN56.G1 70.15,13.69 ; J8.P1B2 77.99,5.38 ; J8.P1B2 78.94,4.44 ; J8.P1B2 77.99,3.49 ; J8.P1B2 77.05,4.44 ; J8.P1B2 78.71,5.15 ; J8.P1B2 77.28,5.15 ; J8.P1B2 77.28,3.72 ; J8.P1B2 78.71,3.72 ; J8.P1B3 81.44,4.44 ; J8.P1B3 81.21,5.15 ; J8.P1B3 79.78,3.72 ; J8.P1B3 79.78,5.15 ; J8.P1B3 80.49,5.38 ; J8.P1B3 81.21,3.72 ; J8.P1B3 79.55,4.44 ; 93.13,5.12 J8.6 ; J8.6 93.29,4.54 ; J8.6 94.62,5.12 ; J8.6 93.29,5.71 ; J8.6 93.87,5.87 ; J8.6 93.87,4.38 ; J8.6 94.46,4.54 ; J8.6 94.46,5.71 ; 82.28,3.72 J8.P1B4 ; J8.P1B4 82.05,4.44 ; J8.P1B4 82.99,5.38 ; J8.P1B4 82.28,5.15 ; J8.P1B4 83.71,5.15 ; J8.P1B4 82.99,3.49 ; J8.P1B4 83.71,3.72 ; J8.P1B4 83.94,4.44 ; J8.2 89.38,5.71 ; J8.2 88.05,5.12 ; J8.2 88.21,5.71 ; J8.2 88.79,4.38 ; J8.2 89.54,5.12 ; J8.2 89.38,4.54 ; J8.2 88.79,5.87 ; J8.2 88.21,4.54 ; CONN56.G2 50.05,13.94 ; CONN56.G2 48.24,14.72 ; CONN56.G2 49.27,15.74 ; CONN56.G2 48.49,15.49 ; CONN56.G2 49.27,13.69 ; CONN56.G2 50.05,15.49 ; CONN56.G2 50.3,14.72 ; CONN56.G2 48.49,13.94
  BOTTOM w0.381: C59.2 19.56,22.34 ; Q6.A 55.79,5.99 v1(56.13,6.33) ; R56.2 22.73,18.27 v1(22.35,18.65) ; C77.2 89.05,25.87 v1(88.9,26.02) ; CB38.2 26.87,19.7 v1(26.55,20.01) ; R52.2 R55.2 v1(22.61,16.24) ; C3.2 v1(92.71,18.4) ; v2(32.89,25.53) 32.77,25.4 v1(32.77,24.62) ; v2(11.64,23.42) 11.43,23.62 11.41,23.62 v1(10.92,24.11) ; v1(88.01,17) 87.07,17.94 C14.2 87.32,18.4 C2.2 ; CB33.2 v1(27.81,22.97) ; C37.1 65.79,27.67 ; v2(60.45,15.11) 62.59,15.11 CB4.1 ; CB27.2 33.2,9.13 v1(32.51,9.13) ; R48.2 v1(22.61,11.16) ; CB30.2 31.55,12.12 v1(31.55,12.12) ; C76.2 80.39,25 ; v2(20.17,8.27) 21.37,8.27 v1(21.46,8.36) ; v1(14.91,17.33) R59.1 13.84,18.53 v2(13.72,18.4) ; R51.2 v1(22.61,13.19) ; v1(6.8,6.01) 7.31,6.01 v2(8,5.32) ; U3.2 v1(87.38,24.11) ; v1(90.68,22.59) 89.85,21.76 Q1.A ; R69.2 v1(89.74,23.28) ; v1(39.5,14.08) 39.37,14.21 CB34.2 ; CB24.2 38.55,3.34 v1(38.35,3.54) ; CB32.2 35.25,13.81 v1(35.45,14.01) ; CB39.2 v1(39.5,13.06) ; v1(32.51,18.02) 32.69,17.84 CB21.2 ; v1(60.38,2.98) C48.2 C68.2 v1(60.38,5.95) ; C78.1 78.61,22.97 ; v1(36.45,15.1) 36.27,15.28 CB35.2 ; CB22.2 41.96,20.5 v1(41.45,21.01) ; CB13.2 68.83,27.67 ; CB36.2 33.27,11.11 32.56,11.11 v1(32.55,11.12) ; 76.28,20.74 C44.2 ; v2(23.75,8.13) 23.75,7.15 CB29.2 v1(22.86,7.1) ; v1(17.02,15.35) 17.65,15.99 C32.1 19.61,15.17 v2(19.43,14.99) ; v1(85.98,22.41) 85.51,21.94 Q4.A ; v1(25.55,5.12) 26.22,4.45 CB18.2 ; v1(31.92,24.67) 31.92,23.79 v2(31.88,23.75) ; C61.2 19.56,23.35 ; 67.06,16.87 66.8,17.13 CB15.2 ; v2(30.99,21.72) 30.88,21.83 v1(30.1,21.83) CB31.2 ; v1(84.2,17.13) 84.25,17.18 C13.2 ; v2(8.76,21.83) 9.8,21.83 v1(10.79,20.83) ; CB28.2 33.79,15.68 v1(34.45,15.01) ; C12.2 50.8,6.48 v1(50.55,6.73) ; v1(41.48,11.99) 41.47,11.99 41.02,11.54 CB25.2 ; v2(27.3,6.48) 26.92,6.48 v1(26.55,6.12) ; v1(41.45,5.12) 41.96,5.62 CB23.2 ; C60.2 19.43,24.37 ; v1(35.45,11.12) 35.73,11.12 36.14,10.7 CB26.2 ; CB16.2 67.82,27.67 ; v1(27.43,12.05) 27.56,12.18 CB20.2 ; CB37.2 v1(39.12,23.86) ; v1(27.43,14.08) 27.69,13.83 CB19.2 ; C22.2 50.55,9.76 50.93,10.14 54.22,10.14 Q9.A 54.26,9.35 v1(54.48,9.13) ; CB17.2 66.8,27.67
  BOTTOM w0.762: CONN56.G1 70.15,15.74 ; CONN56.G1 70.93,15.49 ; CONN56.G1 69.37,13.94 ; CONN56.G1 69.12,14.72 ; CONN56.G1 71.18,14.72 ; CONN56.G1 69.37,15.49 ; CONN56.G1 70.93,13.94
  vias: v1(17.41,23.81) v1(17.41,23.05) v1(18.3,24.57) v1(18.3,23.81) v1(18.3,23.05) v1(61.21,19.67) v1(61.72,27.67) v1(62.1,19.67) v1(62.61,27.8) v1(63.5,27.8) v1(64.39,27.8) v1(72.14,15.6) v1(72.26,17.13) v1(72.26,16.37) v1(72.26,14.72) v1(72.52,13.95) v1(73.41,27.8) v1(73.41,19.16) v1(73.91,27.03) v1(74.42,27.8) v1(74.42,19.16) v1(75.18,27.03) v1(75.31,24.49) v1(75.31,20.68) v1(75.44,27.8) v1(75.56,22.84) v1(76.07,26.65) v1(76.2,25.38) v1(76.2,23.99) v1(76.33,27.8) v1(76.33,22.21) v2(16.26,21.72) v2(17.91,20.7) v2(77.22,22.99) v2(77.47,26.04) v2(78.61,24.51)
25MHZ_OUT: length 4.4
  TOP w0.127: OSC1.3 33.87,27.32 C55.2 R40.2 v1(35.61,27.36)
  BOTTOM w0.127: v2(35.56,26.27) 35.61,26.33 v1(35.61,27.36)
25MHZ_OUT_R: length 11.5
  TOP w0.127: R40.1 34.92,25.51 34.45,25.03 v1(34.45,24.49) 34.45,17.03 34,16.59 U1.H5
  BOTTOM w0.127: v1(34.45,24.49) 34.45,24.02 v2(33.91,23.48)
ALARM1: length 107.3
  TOP w0.127: D3.A 93.29,12.76 95.76,10.29 96.9,10.29 97.54,9.65 97.54,8.76 99.79,6.51 99.79,3.53 97.79,1.52 82.42,1.52 82.11,1.21 74.74,1.21 72.64,3.3 72.64,5.08 69.98,7.75 65.19,7.75 64.01,6.56 64.01,2.92 62.41,1.33 58.75,1.33 58.68,1.4 45.85,1.4 45.59,1.14 33.53,1.14 v1(31.5,3.17) ; U1.F11 35.56,10.12 35.56,9.75 35.56,9.75 35.56,9.4 35.18,9.02 34.8,9.02 34.54,8.76 34.54,4.83 v1(35.18,4.19)
  BOTTOM w0.127: v1(31.5,3.17) 32.22,2.45 35.6,2.45 36.2,3.05 36.2,3.68 35.69,4.19 v1(35.18,4.19)
ALARM1_D: length 2.3
  TOP w0.127: R3.2 91.57,14.04 D3.C
ALARM1_R: length 14.7
  TOP w0.127: J8.17 91.33,10.54 91.25,10.63 91.25,13.75 90.93,14.06 90.93,16.38 91.24,16.69 R3.1 91.64,16.77 C7.1 91.64,18.95 Q2.C2 91.5,19.22 v1(92.33,20.05)
  BOTTOM w0.127: v1(92.33,20.05) 92.33,21.7 91.82,22.21 v2(91.82,22.34)
ALARM2: length 56.1
  TOP w0.127: v1(47.88,10.41) 47.62,10.67 44.7,10.67 44.07,10.03 36.45,10.03 36,9.59 U1.F12
  V3 w0.127: v1(47.88,10.41) 71.44,10.41 v1(72.39,11.37)
  BOTTOM w0.127: v1(72.39,11.37) 85.93,11.37 86.89,12.32 88.27,12.32 89.15,13.21 D1.A
ALARM2_D: length 2.2
  BOTTOM w0.127: D1.C R1.2 88.32,16.42 v2(88.14,16.24)
ALARM2_R: length 14.1
  TOP w0.127: v1(89.92,12.7) 89.92,8.38 90.06,8.23 J8.18
  BOTTOM w0.127: v2(89.79,11.94) 89.92,12.06 v1(89.92,12.7) 89.79,12.83 89.79,16.77 89.23,17.33 R1.1 89.1,17.38 C2.1 89.1,19.32 Q1.C2
ALARM3: length 65.3
  TOP w0.127: v1(44.96,8.51) 44.7,8.51 43.18,6.99 43.18,5.08 42.29,4.19 36.2,4.19 35.56,4.83 35.56,8.25 35.87,8.56 U1.F13 ; D9.A v1(86.87,9.65)
  BOTTOM w0.127: v1(44.96,8.51) 45.47,8 51.18,8 51.56,8.38 53.47,8.38 54.63,7.22 60.82,7.22 61.35,7.75 62.24,7.75 64.26,9.78 83.31,9.78 84.33,8.76 85.72,8.76 86.55,9.59 86.71,9.59 86.77,9.65 v1(86.87,9.65)
ALARM3_D: length 1.1
  TOP w0.127: R16.2 D9.C
ALARM3_R: length 14.6
  TOP w0.127: Q3.C2 86.92,18.48 C10.1 86.92,16.77 R16.1 87.53,16.72 88.14,16.11 88.14,14.84 87.69,14.4 87.69,13.52 88.8,12.41 88.8,9.71 88.79,9.71 J8.19
  BOTTOM w0.127: J8.19 87.63,10.11 v2(87.63,10.97)
ALARM4: length 57.4
  TOP w0.127: U1.F14 36.56,7.01 36.56,5.35 37.34,4.57 42.13,4.57 42.8,5.24 42.8,7.24 v1(44.2,8.64)
  V3 w0.127: v1(44.2,8.64) 44.2,9.14 45.91,10.86 70.42,10.86 v1(72.26,12.7)
  BOTTOM w0.127: D5.A 84.37,14.14 84.2,13.97 84.2,12.95 83.76,12.51 72.95,12.51 72.76,12.7 v1(72.26,12.7)
ALARM4_D: length 2.1
  BOTTOM w0.127: R7.2 D5.C 84.26,15.04 v2(84.07,15.22)
ALARM4_R: length 16.5
  TOP w0.127: v1(85.11,13.46) 85.11,11.79 86.23,10.67 86.23,8.33 J8.20
  BOTTOM w0.127: v1(85.11,13.46) 85.22,13.46 85.47,13.72 85.47,16.87 85.27,17.07 R7.1 84.96,17.53 84.91,17.59 84.91,17.89 C13.1 85.16,18.82 Q4.C2 84.49,19.63 83.19,20.93 v2(83.19,20.95)
BOARD_ID_1: length 6.7
  TOP w0.127: U1.T4 v1(25.27,17.56)
  BOTTOM w0.127: v1(25.27,17.56) 24.82,18.01 24.46,18.01 R56.1 R57.2 24.2,19.85 23.5,20.56 23.11,20.56 22.35,19.8 22.1,19.8 v2(21.84,19.54)
BOARD_ID_2: length 6.7
  TOP w0.127: v1(25.27,16.62) 25.95,16.62 U1.T5
  BOTTOM w0.127: R54.2 24.2,17.56 24,17.76 22.23,17.76 21.46,17 v2(21.46,16.87) ; R54.2 R55.1 ; R54.2 24.64,17.26 v1(25.27,16.62)
CPLD_TCK: length 52
  TOP w0.127: v1(46.1,14.99) 46.1,14.22 47.24,13.08 48.23,13.08 48.9,12.42 48.9,10.26 49.5,9.65 52.72,9.65 53.36,10.29 CONN56.26 ; CONN6.1 14.57,18.53 v1(16.76,18.53) 16.76,18.62 17.81,19.67 21.21,19.67 21.59,19.29 25.4,19.29 25.61,19.07 27.49,19.07 U1.P3 v1(28.52,19.09)
  BOTTOM w0.127: v2(17.65,18.78) 17.02,18.78 v1(16.76,18.53) R59.2 ; v1(46.1,14.99) 45.58,14.46 43.69,14.46 39.5,18.65 36.83,18.65 34.92,20.56 29.21,20.56 28.52,19.87 v1(28.52,19.09)
CPLD_TDI: length 57.3
  TOP w0.127: v1(49.4,18.02) 49.66,18.27 49.66,18.91 50.29,19.54 51.69,19.54 52.09,19.14 CONN56.27 ; U1.L6 v1(30.55,16.01) 23.65,16.01 21.84,14.21 21.84,10.4 20.95,9.51 17.53,9.51 16.89,8.87 16.89,8.49 v1(16.76,8.37) 14.57,8.37 CONN6.9
  BOTTOM w0.127: v2(17.4,7.86) 17.27,7.86 v1(16.76,8.37) R62.1 ; v1(30.55,16.01) 30.55,18.22 31.24,18.91 34.67,18.91 36.45,17.13 39.12,17.13 42.93,13.32 46.47,13.32 47.56,14.41 47.56,17.34 48.24,18.02 v1(49.4,18.02)
CPLD_TDO: length 52.1
  TOP w0.127: v1(47.05,14.99) 47.05,14.03 47.62,13.46 48.39,13.46 49.28,12.57 49.28,10.41 49.66,10.03 51.83,10.03 52.09,10.29 CONN56.28 ; U1.M5 v1(29.55,17.01) 29.55,17.8 29.23,18.12 26.28,18.12 26.21,18.06 25.02,18.06 24.96,18.12 22.07,18.12 21.08,17.13 17.78,17.13 v1(17.02,16.37) 16.64,15.99 14.57,15.99 CONN6.3
  BOTTOM w0.127: v1(29.55,17.01) 29.55,18.36 30.73,19.54 34.67,19.54 36.7,17.51 39.27,17.51 43.08,13.7 46.21,13.7 47.05,14.54 v1(47.05,14.99) ; v2(16.13,16.24) 16.89,16.24 v1(17.02,16.37)
CPLD_TMS: length 55.4
  TOP w0.127: CONN56.25 v1(53.36,19.52) ; CONN6.5 v1(16.76,13.44) 16.76,13.45 16.76,13.95 17.27,14.46 21.08,14.46 21.84,15.22 21.84,16.11 22.85,17.12 v1(28.55,17.12) U1.N4
  BOTTOM w0.127: v1(53.36,19.52) 53.21,19.67 47.35,19.67 46.61,18.92 46.61,14.73 45.96,14.08 43.42,14.08 39.48,18.02 36.83,18.02 34.67,20.18 30.61,20.18 28.55,18.12 v1(28.55,17.12) ; R58.1 15.83,13.44 v1(16.76,13.44) 16.88,13.32 v2(17.65,13.32)
CPU_I2C_R_SCL: length 9.3
  TOP w0.127: U1.C3 39,18.67 39.5,19.16 39.5,20.34 39.51,20.35 39.51,21.08 40.01,21.57 v1(40.01,23.86) 40.01,25.03 R34.2 R33.1
  BOTTOM w0.127: v1(40.01,23.86) 40.01,23.73 40.51,23.22 v2(40.51,22.84)
CPU_I2C_R_SDA: length 8
  TOP w0.127: R36.2 R35.1 37.9,24.7 v1(38.29,24.3) 38.48,24.11 38.48,20.18 39,19.65 U1.C2
  BOTTOM w0.127: v2(37.97,25.13) 38.29,24.81 v1(38.29,24.3)
CPU_I2C_SCL: length 107.2
  TOP w0.127: CONN56.22 55.9,10.76 56.76,9.9 57.02,9.9 v1(57.03,9.89) ; R33.2 v1(41.66,26.07) 41.66,26.04 42.04,25.65 42.04,22.07 43.4,20.7 52.96,20.7 53.98,19.68 53.98,8.76 54.1,8.64 58.29,8.64 58.93,9.27 70.71,9.27 74.13,5.84 81.56,5.84 81.56,5.84 84.77,5.84 86.52,4.1 86.52,2.63 86.87,2.29 90.68,2.29 91.19,2.79 91.19,4.98 J8.4
  BOTTOM w0.127: v1(57.03,9.89) 57.61,10.48 57.61,19.85 57.12,20.35 44.48,20.35 40.77,24.06 v2(40.77,25.13) 40.77,25.51 41.32,26.07 v1(41.66,26.07)
CPU_I2C_SDA: length 111.5
  TOP w0.127: R35.2 v1(37.9,26.86) 37.9,27.61 38.1,27.81 41.53,27.81 42.42,26.92 42.42,22.23 43.56,21.08 54.48,21.08 55.26,20.31 55.26,9.64 55.88,9.02 58.04,9.02 58.67,9.65 70.87,9.65 74.29,6.23 81.72,6.23 81.72,6.22 85.76,6.22 88.01,3.98 89.3,3.98 J8.3 ; CONN56.20 57.17,10.52 v1(57.78,9.91)
  BOTTOM w0.127: v1(37.9,26.86) 38.1,26.65 v2(39.24,26.65) 41.7,26.65 42.1,26.25 42.1,25.88 41.72,25.5 41.72,23.64 44.63,20.73 57.28,20.73 57.99,20.01 57.99,19.69 57.99,10.03 57.87,9.91 v1(57.78,9.91)
FAN1_CTL_R: length 21.5
  TOP w0.127: Q2.C1 89.74,18.83 C8.1 89.74,17.35 89.53,17.14 R4.2 90.11,16.69 90.32,16.49 90.32,14.14 90.87,13.59 v1(90.87,10.03) 90.5,9.66 90.5,8.6 91.22,7.87 92.95,7.87 95.14,5.68 J8.7
  BOTTOM w0.127: v2(91.57,11.18) 91.57,10.73 v1(90.87,10.03)
FAN1_SENSOR: length 19.4
  TOP w0.127: D2.A 54.73,8.05 R20.1 54.17,7.93 52.98,9.13 v1(45.47,9.13) 41.19,9.13 41.19,9.12 38.82,9.12 38.81,9.13 38.48,9.13 38,8.65 U1.D13
  BOTTOM w0.127: v2(46.1,8.62) 45.59,9.13 v1(45.47,9.13)
FAN1_SENSOR_D: length 3.8
  TOP w0.127: D2.C 56.76,7.15 R5.2 v1(56.9,6.21)
  BOTTOM w0.127: v1(56.9,6.21) 56.15,5.46 56.13,5.46 55.98,5.31 55.53,5.31 v2(55.52,5.29)
FAN1_SENSOR_R: length 52.6
  TOP w0.127: R5.1 C9.1 58.4,7.93 58.64,7.69 Q5.C1 60.04,7.69 60.79,8.44 v1(61.98,8.44) 62.42,8.89 70.48,8.89 73.91,5.46 81.4,5.46 81.79,5.08 v1(81.79,1.78)
  BOTTOM w0.127: v2(61.98,10.03) v1(61.98,8.44) ; J8.12 97.68,6.27 97.69,6.27 97.69,4.78 96.52,3.61 96.52,2.02 95.97,1.46 82.11,1.46 v1(81.79,1.78)
FAN2_CTL_R: length 23.4
  TOP w0.127: v1(93.85,11.43) 95.25,10.03 95.25,8.51 96.41,7.34 J8.8
  BOTTOM w0.127: v2(91.97,24.73) 91.95,24.73 91.82,24.61 91.82,23.34 91.19,22.7 91.19,21.7 90.72,21.23 Q1.C1 90.6,19.61 C3.1 90.6,17.38 R2.2 91.76,17.33 93.85,15.24 v1(93.85,11.43)
FAN2_SENSOR: length 32.3
  TOP w0.127: U1.K11 v1(31.55,10.12)
  BOTTOM w0.127: D7.A 47.99,8.68 47.87,8.8 R26.1 46.73,8.8 46.34,9.19 46.18,9.19 45.8,9.57 44.37,9.57 43.18,8.38 43.18,4.32 v2(42.55,3.68) 42.55,2.78 41.8,2.03 31.91,2.03 30.93,3.01 30.93,8.46 31.55,9.07 v1(31.55,10.12)
FAN2_SENSOR_D: length 2.4
  BOTTOM w0.127: D7.C 49.4,9.58 R10.2 49.53,10.02 v2(48.9,10.65)
FAN2_SENSOR_R: length 52.7
  BOTTOM w0.127: J8.13 94.95,10.41 94.23,10.41 92.84,11.81 91.34,11.81 90.46,10.92 89.25,10.92 88.63,11.54 87.39,11.54 87.06,11.2 87.06,10.48 86.55,9.97 85.03,9.97 84.84,10.16 71.37,10.16 70.93,10.6 61.53,10.6 60.96,10.03 60.96,8.62 v2(60.83,8.49) 60.13,7.79 54.69,7.79 53.32,9.17 Q9.C1 51.53,9.17 51.16,8.8 C22.1 R10.1
FAN3_CTL_R: length 29.3
  TOP w0.127: J8.9 96.47,2 94.64,2 93.44,3.19 93.44,3.56 92.2,4.8 92.2,5.44 91.68,5.96 90.99,5.96 90.84,5.82 89.31,5.82 88.9,6.22 87.9,6.22 87.87,6.2 87.18,6.2 86.69,6.69 85.72,7.65 v1(85.72,9.4) 85.72,9.65 84.2,11.18 84.2,15.3 85.67,16.77 ; 85.67,16.77 R15.2 ; 85.67,16.77 C11.1 85.67,19.11 Q3.C1
  BOTTOM w0.127: v2(84.84,9.4) v1(85.72,9.4)
FAN3_SENSOR: length 28.2
  TOP w0.127: U1.L12 v1(30.55,9.12)
  BOTTOM w0.127: v1(30.55,9.12) 30.55,2.85 31.75,1.65 44.16,1.65 R22.1 47.62,4.87 D4.A v2(49.55,3.96)
FAN3_SENSOR_D: length 2.4
  BOTTOM w0.127: v2(49.66,7.1) 49.78,6.97 R6.2 49.65,5.77 D4.C
FAN3_SENSOR_R: length 52.7
  BOTTOM w0.127: R6.1 C12.1 50.81,4.98 Q6.C1 52.51,4.69 55.38,4.69 55.63,4.45 58.55,4.45 59.25,5.14 v2(59.25,6.19) 59.9,6.84 61.45,6.84 61.98,7.37 62.49,7.37 64.39,9.27 83.28,9.27 84.45,8.11 92.05,8.11 92.84,8.89 92.84,9.65 93.09,9.91 94.87,9.91 95.25,9.53 95.25,7.14 J8.14
FAN4_CTL_R: length 31.3
  TOP w0.127: v1(87.5,14.84) 87.31,14.65 87.31,13.29 87.91,12.69 87.91,8.01 89.72,6.2 90.68,6.2 90.83,6.34 91.84,6.34 93.04,5.15 93.04,4.51 93.82,3.72 93.82,3.35 94.8,2.38 95.66,2.38 98.41,5.12 J8.10
  BOTTOM w0.127: v2(87.5,22.34) 86.52,21.35 Q4.C1 86.16,19.13 C14.1 86.11,18.09 R8.2 86.29,17.07 86.74,16.62 86.74,15.37 87.27,14.84 v1(87.5,14.84)
FAN4_SENSOR: length 24.1
  TOP w0.127: D8.A 46.35,8.1 R44.1 46.23,7.98 45.7,7.98 44.7,6.98 v1(44.7,5.83) 44.45,5.57 44.45,2.76 43.97,2.29 42.15,2.29 41.9,2.54 33.88,2.54 31.97,4.45 31.37,4.45 31,4.81 U1.L16
  BOTTOM w0.127: v2(43.8,5.34) 43.81,5.35 43.81,5.46 44.18,5.83 v1(44.7,5.83)
FAN4_SENSOR_D: length 3.1
  TOP w0.127: v1(48.13,6.33) 48.13,6.46 48.51,6.84 R11.2 48.38,7.2 D8.C
  BOTTOM w0.127: v2(47.75,7.22) 48.13,6.84 v1(48.13,6.33)
FAN4_SENSOR_R: length 60.7
  TOP w0.127: R11.1 C23.1 50.02,7.98 50.26,7.74 Q10.C1 50.96,7.21 52.21,5.95 52.96,5.95 53.7,5.21 v1(58.42,5.21) 58.81,4.83 61.73,4.83 65.04,8.13 70.17,8.13 73.15,5.15 73.15,3.56 74.68,2.03 v1(79.38,2.03)
  BOTTOM w0.127: v1(79.38,2.03) 81.15,2.03 81.41,2.29 85.85,2.29 86.3,1.84 93.66,1.84 94.11,2.29 94.11,3.81 94.74,4.44 94.74,5.71 93.87,6.58 J8.15 ; v1(58.42,5.21) 57.54,5.21 v2(57.53,5.21)
FAN5_CTL_R: length 57.1
  TOP w0.127: v1(63.36,5.83) 63.36,5.43 61.99,4.06 Q7.C1 58.64,4.06 58.45,4.25 C16.1 R18.2
  BOTTOM w0.127: J8.11 100.2,7.7 v2(100.2,6.99) 100.52,6.67 100.52,1.83 99.78,1.08 76.52,1.08 69.22,8.38 65.92,8.38 v1(63.36,5.83)
FAN5_SENSOR: length 27.3
  TOP w0.127: D6.A 46.35,4.5 R24.1 46.15,4.3 45.59,4.3 45.47,4.17 v1(45.47,3.79) 45.47,2.7 44.29,1.52 41.84,1.52 41.58,1.78 33.56,1.78 31.66,3.68 29.97,3.68 28.55,5.1 28.55,8.12 U1.N13
  BOTTOM w0.127: v1(45.47,3.79) 44.97,3.3 44.43,3.3 v2(44.41,3.28)
FAN5_SENSOR_D: length 3.3
  TOP w0.127: D6.C 47.5,3.47 R9.2 v1(48.51,2.65)
  BOTTOM w0.127: v1(48.51,2.65) 48.15,2.65 v2(47.5,3.3)
FAN5_SENSOR_R: length 57.6
  TOP w0.127: v1(54.93,2.72) 53.51,4.13 Q8.C1 50.26,4.13 50.02,4.37 C17.1 R9.1
  BOTTOM w0.127: v2(54.1,3.3) 54.34,3.3 v1(54.93,2.72) 56.28,4.06 59.05,4.06 59.82,4.83 59.82,6.21 60.07,6.46 62.99,6.46 65.29,8.76 69.47,8.76 75.69,2.54 81.03,2.54 81.15,2.67 86.11,2.67 86.55,2.22 92.8,2.22 93.47,2.9 93.47,3.68 92.6,4.55 J8.16
FAN_1V8: length 11.1
  TOP w0.381: U1.H10 v1(34.45,11.12) ; R45.1 v1(23.75,25) ; U1.H8 v1(34.45,14.01) ; U1.J9 v1(32.55,12.12) ; U1.J7 v1(32.55,15.01)
  BOTTOM w0.381: v1(32.55,15.01) 32.8,14.77 CB28.1 ; v1(22.1,22.08) 21.84,22.34 C59.1 ; C61.1 21.84,23.35 v1(22.1,23.61) ; v1(32.55,12.12) 32.46,12.21 CB30.1 ; v1(22.1,24.24) 21.97,24.37 C60.1 ; v1(34.45,14.01) 34.34,13.91 CB32.1 ; v1(34.45,11.12) 35.23,10.33 CB26.1
  vias: v1(22.1,22.84) v1(22.73,23.86) v1(22.73,22.21) v1(22.86,22.97) v2(22.86,21.19)
FAN_IDLE: length 31.7
  TOP w0.127: CONN56.19 v1(57.17,19.67) 57.17,20.07 57.4,20.3 R38.1 R39.2 ; U1.E13 v1(37.45,8.12)
  BOTTOM w0.127: v1(57.17,19.67) 56.92,19.92 55.37,19.92 v2(52.32,16.87) 48.37,16.87 47.94,16.45 47.94,14.26 46.62,12.94 43.26,12.94 39.59,9.27 38.61,9.27 v1(37.45,8.12)
FAN_IN_3V3_25M_EN: length 3.3
  TOP w0.127: OSC1.1 29.97,25.51 R41.2 v1(28.65,24.8)
  BOTTOM w0.127: v2(29.21,24.11) 28.65,24.67 v1(28.65,24.8)
FAN_IN_3V3_25M_VCC: length 5.4
  TOP w0.127: L3.1 27.18,27.42 v1(26.8,27.8)
  TOP w0.381: L3.1 27.23,26.96 C51.1 29.82,26.96 OSC1.4
  BOTTOM w0.127: v2(26.67,26.65) 26.8,26.78 v1(26.8,27.8)
FAN_IN_3V3_EN: length 3
  TOP w0.381: U2.2 v1(14.02,24.44)
  BOTTOM w0.127: v2(13.21,24.49) 13.97,24.49 v1(14.02,24.44)
  BOTTOM w0.381: R61.1 14.86,24.44 v1(14.02,24.44)
FAN_INT: length 27.6
  TOP w0.127: CONN56.21 v1(55.9,19.46) ; U1.E14 v1(37.45,7.12)
  BOTTOM w0.127: v1(37.45,7.12) 37.48,7.12 39.13,8.76 39.62,8.76 43.42,12.56 46.97,12.56 48.01,13.6 50.78,13.6 54.94,17.76 v2(55.9,17.76) v1(55.9,19.46)
FAN_PRESENT: length 83.5
  TOP w0.127: v1(58.29,2.14) 58.43,2.28 59.08,2.28 Q7.C2 ; U1.J16 v1(33.58,4.99) 33.58,3.38 34.04,2.92 42.06,2.92 42.31,2.67 43.81,2.67 44.07,2.92 44.07,7.04 v1(44.8,7.76) 44.94,7.76 45.87,8.69 52.56,8.69 53.72,7.53 53.72,6.71 54.74,5.7 58.02,5.7 v1(58.17,5.84) 59.17,6.84 59.82,6.84 60.71,7.73 62.36,7.73 63.14,8.51 70.33,8.51 73.53,5.3 73.53,3.94 74.3,3.17 80.64,3.17 v1(80.77,3.05)
  V3 w0.127: v1(58.29,2.14) 58.29,4.19 57.74,4.74 57.74,5.42 v1(58.17,5.84)
  BOTTOM w0.127: v2(56.77,3.3) 56.77,2.79 57.21,2.35 57.21,2.34 57.47,2.08 58.23,2.08 v1(58.29,2.14) ; R23.1 33.58,4.7 v1(33.58,4.99) ; J8.5 91.76,4.06 87,4.06 85.98,3.05 v1(80.77,3.05) ; v2(44.11,7.22) 44.11,7.26 44.61,7.76 v1(44.8,7.76)
FAN_PW_EN: length 5.8
  TOP w0.127: R37.1 v1(36.91,24.24) 36.91,20.66 U1.E1
  BOTTOM w0.127: v2(36.58,23.22) 36.91,23.55 v1(36.91,24.24)
FAN_PW_EN_R: length 65.9
  TOP w0.127: R37.2 v1(36.91,27.42)
  BOTTOM w0.127: v1(36.91,27.42) 37.22,27.73 41.16,27.73 42.48,26.41 42.48,25.72 42.1,25.34 42.1,23.8 44.79,21.11 53.77,21.11 60.96,28.3 87.9,28.3 90.17,26.04 v2(90.17,25.65) 90.17,25 89.53,24.37 89.1,24.37 R65.2
FAN_PWM_1: length 65.4
  TOP w0.127: v1(88.14,13.7) 88.14,14.21 88.72,14.79 R13.2 R4.1 ; U1.C14 v1(39.46,8.02)
  BOTTOM w0.127: v1(39.46,8.02) 43.61,12.18 47.13,12.18 48.17,13.22 50.94,13.22 53.81,16.09 56.41,16.09 56.9,15.6 56.9,12.57 v2(56.52,12.19) 56.26,11.94 56.26,9.77 56.71,9.32 57.97,9.32 58.42,9.77 58.42,10.67 60.01,12.26 72.67,12.26 72.79,12.13 85.62,12.13 87.19,13.7 v1(88.14,13.7)
FAN_PWM_2: length 77.2
  TOP w0.127: U1.J15 v1(33.45,6.12)
  BOTTOM w0.127: 54.74,14.94 54.91,14.94 55.5,14.35 55.5,9.45 56.4,8.56 58.91,8.56 59.69,9.33 59.69,10.41 60.64,11.37 71.56,11.37 72.01,10.92 86.36,10.92 86.68,11.24 86.68,11.36 87.24,11.92 88.79,11.92 89.41,11.3 90.3,11.3 92.71,13.72 92.71,14.6 91.89,15.42 R12.2 R2.1 ; 54.74,14.94 v2(54.75,14.95) ; 54.74,14.94 54.04,14.94 51.54,12.45 48.54,12.45 47.51,11.41 44.02,11.41 38.72,6.12 v1(33.45,6.12)
FAN_PWM_3: length 70.2
  TOP w0.127: R15.1 R21.2 85.17,14.81 84.66,14.3 84.66,11.48 v1(85.72,10.41) ; U1.K16 v1(32.57,5)
  BOTTOM w0.127: v1(32.57,5) 33.15,5.57 38.72,5.57 44.18,11.03 47.67,11.03 48.7,12.06 51.7,12.06 52.93,13.3 54.46,13.3 v2(54.71,13.05) 55.12,12.64 55.12,9.29 56.24,8.17 59.5,8.17 60.2,8.87 60.2,10.03 61.15,10.99 71.18,10.99 71.63,10.54 85.09,10.54 85.22,10.41 v1(85.72,10.41)
FAN_PWM_4: length 74.9
  TOP w0.127: U1.L14 v1(31.45,7.12)
  BOTTOM w0.127: v1(31.45,7.12) 31.9,6.67 38.74,6.67 43.86,11.79 47.35,11.79 48.39,12.83 51.39,12.83 54.14,15.58 55.67,15.58 55.88,15.37 55.88,9.61 56.55,8.94 58.48,8.94 59.11,9.56 v2(59.11,9.81) 59.11,10.59 60.39,11.87 72.51,11.87 72.63,11.75 85.78,11.75 87.17,13.14 88.21,13.14 88.58,13.52 88.58,14.08 88.46,14.21 87.07,14.21 86.49,14.79 86.49,14.87 86.45,14.91 86.37,14.91 R14.2 R8.1
FAN_PWM_5: length 34.7
  TOP w0.127: U1.M15 29.55,6.12 29.55,5.12 30.61,4.06 31.82,4.06 33.72,2.16 41.74,2.16 41.99,1.91 44.13,1.91 44.83,2.61 44.83,4.94 45.47,5.57 v1(46.1,5.57) 48.9,5.57 49.51,4.95 53.32,4.95 54.94,3.34 R25.2 R18.1
  BOTTOM w0.127: v1(46.1,5.57) v2(46.1,4.68)
FAN_VP3P3: length 73.5
  TOP w0.381: L3.2 25.33,26.58 C56.1 v1(25.33,24.95) ; R39.1 v1(56.39,22.72) ; 61.98,23.88 61.99,23.86 CB55.1 ; C54.2 59.82,22.97 ; U1.L8 30.63,13.19 30.52,13.19 v1(30.5,13.17) ; CB54.1 59.82,24.11 ; v1(39.88,27.16) R34.1 39.85,26.09 R36.1 ; R25.1 v1(54.94,4.25) ; R41.1 v1(27.05,25.51) ; R13.1 89.63,13.88 90.17,13.34 v1(90.3,13.34) ; U1.J6 v1(32.55,16.01) ; R21.1 v1(85.72,12.95) ; R24.2 v1(46.23,2.65) ; U1.P16 v1(27.55,5.12) ; v1(21.38,15.99) 19.22,15.99 CONN6.4 ; U1.L9 v1(30.55,12.12) ; 59.94,21.83 C53.2 59.26,21.12 59.31,21.07 ; U1.T14 v1(25.55,7.12) ; U1.A14 v1(41.45,7.12) ; C75.1 13.08,23.1 ; U1.F9 v1(36.45,12.12) ; U1.H11 v1(34.45,10.12) ; v1(55.5,6.59) 55.24,6.59 54.81,7.02 R20.2 ; R44.2 46.23,6.46 v1(46.48,6.21) ; C52.2 62.09,24.88 61.98,24.77 ; U1.A3 v1(41.45,19.01) ; U1.T3 25.23,18.56 25.15,18.65 v1(24.89,18.65) ; C74.1 13.21,24.11 ; U1.F8 v1(36.45,14.01) ; v1(28.49,20.97) 28.45,20.97 28.41,20.94 28.38,20.94 U1.P1 ; U1.C1 v1(39,21.32) ; U1.C16 v1(39.45,5.12) ; U1.J11 v1(32.55,10.12) ; U1.H6 v1(34.45,16.01)
  V3 w0.508: J8.1 88.11,2.63 ; J8.1 86.94,2.63 ; J8.1 88.27,3.21 ; J8.1 86.94,3.8 ; J8.1 88.11,3.8 ; J8.1 87.52,2.47 ; J8.1 87.52,3.96 ; J8.1 86.78,3.21
  BOTTOM w0.381: v1(85.72,12.95) 85.72,13.08 86.11,13.46 R14.1 ; v1(30.5,13.17) 30.5,13.17 30.32,13.17 CB19.1 ; v1(13.72,22.59) 14.53,23.4 R61.2 ; CB21.1 33.27,16.73 v1(32.55,16.01) ; CB12.1 62.36,22.84 62.1,23.1 ; CB24.1 39.37,5.03 v1(39.45,5.12) ; R26.2 v1(46.41,9.71) ; R49.1 v1(22.61,10.14) ; C32.2 v1(21.38,15.99) ; v1(28.49,20.97) 28.49,21.81 CB31.1 ; v1(34.45,16.01) 34.48,15.99 CB35.1 ; R22.2 46.79,5.9 v1(46.48,6.21) ; v1(34.45,10.12) 34.24,9.9 CB27.1 ; CB18.1 27.12,4.69 v1(27.55,5.12) ; CB22.1 42.03,19.59 v1(41.45,19.01) ; R12.1 90.3,14.26 v1(90.3,13.34) ; v1(25.55,7.12) 25.53,7.1 CB29.1 ; CB25.1 37.03,11.54 v1(36.45,12.12) 37.26,12.93 CB39.1 ; v1(39,21.32) 39.12,21.43 CB37.1 ; C38.1 62.61,24.49 ; v1(41.45,7.12) 42.03,6.53 CB23.1 ; R62.2 v1(14.91,7.3) ; v1(35.56,3.41) 35.11,2.96 R23.2 ; CB8.1 61.34,22.97 ; C40.1 62.61,26.53 ; CB36.1 33.27,10.2 32.64,10.2 v1(32.55,10.12) ; CB9.1 59.31,23.1 ; v1(30.55,12.12) 30.49,12.18 CB20.1 ; R57.1 v1(23.29,20) ; CB11.1 60.33,23.1 ; CB38.1 25.4,18.4 25.15,18.65 v1(24.89,18.65) ; v1(36.45,14.01) 36.65,14.21 CB34.1 ; R54.1 v1(22.35,17.26) ; CB10.1 62.74,23.48 ; C41.1 58.29,23.1 ; R53.1 v1(22.61,14.21) ; C39.1 62.61,25.51 ; R50.1 v1(22.61,12.18) ; R58.2 v1(14.91,12.23)
  vias: v1(13.21,22.08) v1(13.34,21.32) v1(13.84,21.83) v1(60.07,26.4) v1(60.07,25.51) v1(60.71,25.38) v1(60.83,26.27) v1(61.47,25.26) v1(61.72,26.02) v2(59.44,24.49)
